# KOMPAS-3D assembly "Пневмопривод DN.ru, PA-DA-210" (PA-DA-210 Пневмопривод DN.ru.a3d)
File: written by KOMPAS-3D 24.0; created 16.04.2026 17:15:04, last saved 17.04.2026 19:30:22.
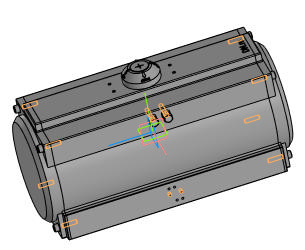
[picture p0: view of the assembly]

Document properties: Автор: DN.ru; Полное имя файла: C:\Работа\PA-DA-х Пневмопривод DN.ru\210\исходные материалы\PA-DA-210 Пневмопривод DN.ru.a3d

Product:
- Component [detail]: Пневмопривод DN.ru  | designation PA-DA-210  | qty 1  | pos. 1  | Масса: 47; Раздел спецификации: Прочие изделия; Примечание: D290-00300; Автор: DN.ru; source file: PA-DA-210 Пневмопривод DN.ru.m3d
- Component [standard]: Болт М10-6gx50 ГОСТ 7805-70  | qty 1  | pos. 2  | Масса: 0.04195; Раздел спецификации: Стандартные изделия; Рассекать на разрезах: no
- Component [standard]: Болт М10-6gx50 ГОСТ 7805-70  | qty 1  | Масса: 0.04195; Раздел спецификации: Стандартные изделия; Рассекать на разрезах: no
- Component [standard]: Гайка М10-6H ГОСТ 5915-70  | qty 1  | pos. 3  | Масса: 0.01206; Раздел спецификации: Стандартные изделия; Рассекать на разрезах: no
- Component [standard]: Гайка М10-6H ГОСТ 5915-70  | qty 1  | Масса: 0.01206; Раздел спецификации: Стандартные изделия; Рассекать на разрезах: no
- Component [standard]: Винт М10-6gx40 ГОСТ 11738-84  | qty 8  | Масса: 0.03345; Раздел спецификации: Стандартные изделия; Рассекать на разрезах: no
- Part/product: Пневмопривод DN.ru  | designation PA-DA-210
    Масса: 47
    Раздел спецификации: Прочие изделия
    Примечание: D290-00300

Expressions: D290-00300
Referenced files in C:\Работа\PA-DA-х Пневмопривод DN.ru\210\исходные материалы\: PA-DA-210 Пневмопривод DN.ru.m3d
Referenced files in C:\Program Files\ASCON\KOMPAS-3D v24\Libs\PolynomLib\DATA\vault\Methods\Kompas\3D\: PLib_Bolt_1_900.m3d, PLib_Nut_OST92_900.m3d, PLib_Screw_GOST_11738_1500.m3d
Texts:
  PA-DA-210
  Крепежное изделие ГОСТ
  BOSimple***PART:f6352c65-8636-7196-6402-d592979e6031***SHORTLOC:Root±30±20±10±80±10±©{}30±©{BASE}130±30[Нет;Без покрытия;Без указания материала;50;10;17;1,5;-]
  BOSimple***PART:2c395b93-8c4a-cf39-bcf6-f45056cee6ca***SHORTLOC:Root±30±10±20±©{}110±10±50±60[Нет;Без покрытия;Без указания материала;-;10;1,5;17]
  BOSimple***PART:011d863b-f530-88e0-fdd6-78b6a69773f1***SHORTLOC:Root±30±20±10±80±10±GMC90[Нет;Без покрытия;Без указания материала;1,5;-;40;10]
  Программные изделия  и базы данных
  PA-DA-210 Пневмопривод DN.ru
  Болт М10-6gx50 ГОСТ 7805-70 (1)
  hole1
  hole2
  Болт М10-6gx50 ГОСТ 7805-70 (2)
  Гайка М10-6H ГОСТ 5915-70 (1)
  bcut1
  hcut1
  cut1
  Гайка М10-6H ГОСТ 5915-70 (2)
  Винт М10-6gx40 ГОСТ 11738-84 (1)
  Винт М10-6gx40 ГОСТ 11738-84 (2)
  Винт М10-6gx40 ГОСТ 11738-84 (3)
  Винт М10-6gx40 ГОСТ 11738-84 (4)
  Винт М10-6gx40 ГОСТ 11738-84 (5)
  Винт М10-6gx40 ГОСТ 11738-84 (6)
  Винт М10-6gx40 ГОСТ 11738-84 (7)
  Винт М10-6gx40 ГОСТ 11738-84 (8)
  Plane. Начало координат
